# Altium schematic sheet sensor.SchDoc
size A4
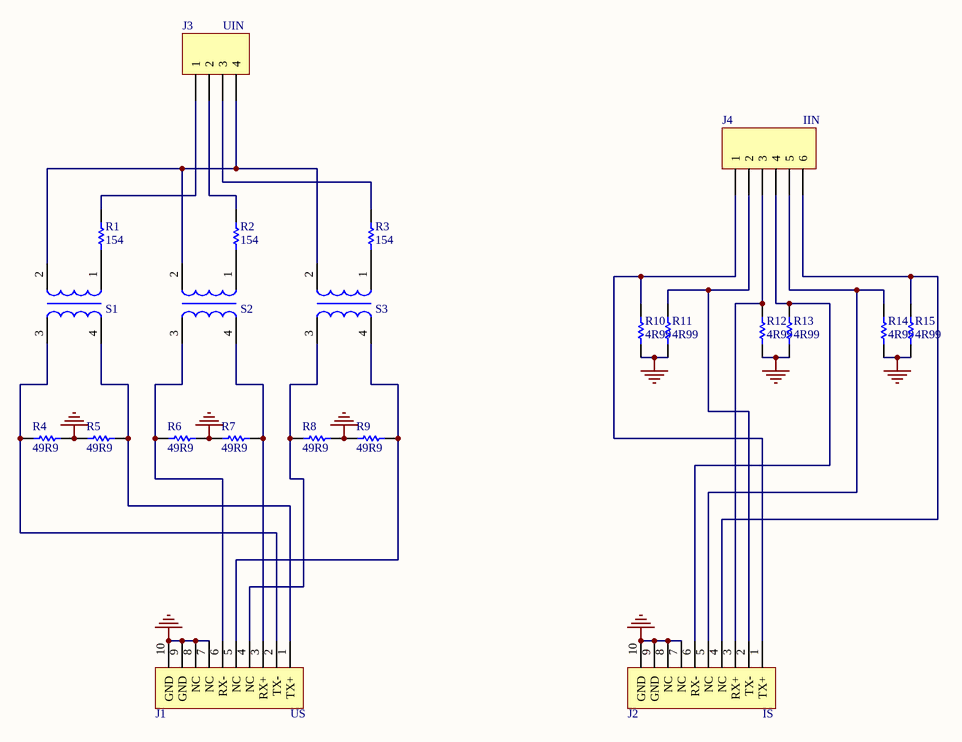
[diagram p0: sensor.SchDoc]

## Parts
J1  US  [RJ-45]
J2  IS  [RJ-45]
J3  UIN  [2EDG-3.81-4P]
J4  IIN  [2EDG-3.81-6P]
R1  154  [R1W]
R2  154  [R1W]
R3  154  [R1W]
R4  49R9  [0805]
R5  49R9  [0805]
R6  49R9  [0805]
R7  49R9  [0805]
R8  49R9  [0805]
R9  49R9  [0805]
R10  4R99  [0805]
R11  4R99  [0805]
R12  4R99  [0805]
R13  4R99  [0805]
R14  4R99  [0805]
R15  4R99  [0805]
S1  US  [US]  (value not drawn)
S2  US  [US]  (value not drawn)
S3  US  [US]  (value not drawn)

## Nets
GND: J1.7(NC) J1.8(NC) J1.9(GND) J1.10(GND) J2.7(NC) J2.8(NC) J2.9(GND) J2.10(GND) R4.1 R5.2 R6.1 R7.2 R8.1 R9.2 R10.1 R11.1 R12.1 R13.1 R14.1 R15.1
NetJ1_1: J1.1(TX+) R5.1 S1.4
NetJ1_2: J1.2(TX-) R4.2 S1.3
NetJ1_3: J1.3(RX+) R7.1 S2.4
NetJ1_4: J1.4(NC) R8.2 S3.3
NetJ1_5: J1.5(NC) R9.1 S3.4
NetJ1_6: J1.6(RX-) R6.2 S2.3
NetJ2_1: J2.1(TX+) J4.1 R10.2
NetJ2_2: J2.2(TX-) J4.2 R11.2
NetJ2_3: J2.3(RX+) J4.3 R12.2
NetJ2_4: J2.4(NC) J4.6 R15.2
NetJ2_5: J2.5(NC) J4.5 R14.2
NetJ2_6: J2.6(RX-) J4.4 R13.2
NetJ3_1: J3.1 R1.2
NetJ3_2: J3.2 R2.2
NetJ3_3: J3.3 R3.2
NetJ3_4: J3.4 S1.2 S2.2 S3.2
NetR1_1: R1.1 S1.1
NetR2_1: R2.1 S2.1
NetR3_1: R3.1 S3.1

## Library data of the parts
J1 J2 = RJ45: RJ45水晶座
J3 = MHDR1X4: Header, 4-Pin
J4 = MHDR1X6: Header, 6-Pin
R1-R3 = Res: 电阻
R4-R15 = Res: Resistor
S1-S3 = US: 电压互感器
